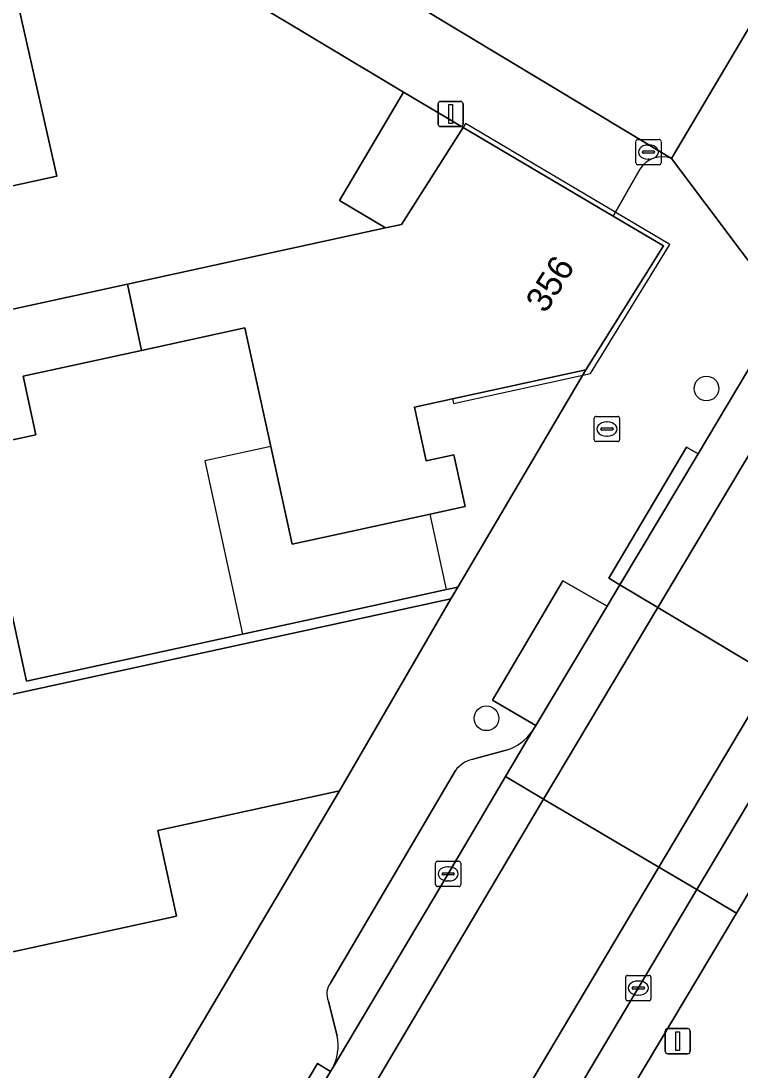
# Model space of a CAD drawing. Extents: x 160554 to 161248, y 385329 to 386506.
# Drawn here: x 160800.82 to 160829.3, y 385754.9 to 385796.49 of the extents above; entities that cross this region are included whole.
import ezdxf

# ---------------------------------------------------------------- set-up
doc = ezdxf.new("R2010")
doc.units = 0
for name, color, linetype in [('IMGEO_Boom', 7, 'Continuous'), ('IMGEO_Brandkraan', 7, 'Continuous'), ('IMGEO_Erf', 7, 'Continuous'), ('IMGEO_Kolk', 7, 'Continuous'), ('IMGEO_Lichtmast', 7, 'Continuous'), ('IMGEO_Pand', 7, 'Continuous'), ('IMGEO_Pand_nummerreeks', 7, 'Continuous'), ('IMGEO_Pand_overbouw', 7, 'Continuous'), ('IMGEO_Parkeervlak_open', 7, 'Continuous'), ('IMGEO_Rijbaan_lokaal_gesloten', 7, 'Continuous'), ('IMGEO_Rijbaan_lokaal_open', 7, 'Continuous'), ('IMGEO_Voetpad_open', 7, 'Continuous')]:
    doc.layers.add(name, color=color, linetype=linetype)

msp = doc.modelspace()

# ---------------------------------------------------------------- linework, layer by layer
at = {"layer": 'IMGEO_Boom'}
for centre in [(160827.97, 385781.916), (160819.254, 385768.842)]:
    msp.add_circle(centre, 0.489, dxfattribs=at)
at = {"layer": 'IMGEO_Brandkraan'}
for p, q in [((160823.526, 385779.884), (160823.526, 385780.736)), ((160823.601, 385780.81), (160824.453, 385780.81)), ((160824.014, 385780.59), (160824.039, 385780.59)), ((160824.527, 385780.736), (160824.527, 385779.884)), ((160823.785, 385780.304), (160823.785, 385780.316)), ((160824.223, 385780.267), (160823.825, 385780.267)), ((160823.828, 385780.353), (160824.226, 385780.353)), ((160824.037, 385780.03), (160824.012, 385780.03)), ((160824.269, 385780.316), (160824.269, 385780.304)), ((160824.453, 385779.81), (160823.601, 385779.81))]:
    msp.add_line(p, q, dxfattribs=at)
for points in [[(160823.526, 385779.884), (160823.526, 385780.736)], [(160823.601, 385780.81), (160824.453, 385780.81)], [(160824.527, 385780.736), (160824.527, 385779.884)], [(160824.453, 385779.81), (160823.601, 385779.81)]]:
    msp.add_lwpolyline(points, dxfattribs=at)
for centre, radius, start, end in [((160823.603, 385780.734), 0.0765, 91.552, 178.448), ((160823.603, 385780.734), 0.0765, 91.552, 178.448), ((160824.451, 385780.734), 0.0765, 1.552, 88.448), ((160824.451, 385780.734), 0.0765, 1.552, 88.448), ((160823.825, 385780.313), 0.0403, 85.8775, 175.7526), ((160823.822, 385780.303), 0.0366, 178.938, 274.7102), ((160824.226, 385780.31), 0.043, 264.8664, 352.4533), ((160824.23, 385780.315), 0.0386, 1.7309, 96.639), ((160823.603, 385779.886), 0.0765, 181.552, 268.448), ((160823.603, 385779.886), 0.0765, 181.552, 268.448), ((160824.451, 385779.886), 0.0765, 271.552, 358.448), ((160824.451, 385779.886), 0.0765, 271.552, 358.448)]:
    msp.add_arc(centre, radius, start, end, dxfattribs=at)
for centre, major_axis, ratio, start_param, end_param in [((160824.013, 385780.31), (-0.387, 0.002), 0.722429, 4.712389, 7.853982), ((160824.038, 385780.31), (-0.39, 0.002), 0.717154, 1.570796, 4.712389)]:
    msp.add_ellipse(centre, major_axis=major_axis, ratio=ratio, start_param=start_param, end_param=end_param, dxfattribs=at)
at = {"layer": 'IMGEO_Erf'}
for points in [[(160797.582, 385839.533), (160777.43, 385835.122), (160782.162, 385813.51), (160796.35, 385816.614), (160798.295, 385807.928), (160800.447, 385798.314), (160802.235, 385790.33), (160796.019, 385788.976), (160795.316, 385792.204), (160792.549, 385791.601), (160793.252, 385788.373), (160788.797, 385787.403), (160789.812, 385782.742), (160805.036, 385786.057), (160815.262, 385788.283), (160813.432, 385789.365), (160815.971, 385793.66), (160806.321, 385799.472)], [(160810.713, 385779.615), (160809.689, 385784.319), (160805.594, 385783.427), (160800.899, 385782.404), (160801.404, 385780.084), (160799.016, 385779.564), (160801.029, 385770.319), (160809.595, 385772.184), (160813.231, 385772.976), (160817.678, 385773.945), (160818.116, 385774.04), (160823.188, 385782.657), (160817.906, 385781.507), (160816.398, 385781.179), (160816.438, 385780.994), (160816.862, 385779.044), (160817.967, 385779.285), (160818.413, 385777.239), (160817.026, 385776.937), (160813.931, 385776.263), (160811.555, 385775.746)], [(160813.435, 385765.968), (160806.234, 385764.4), (160806.975, 385761), (160794.84, 385758.356), (160796.659, 385750), (160798.402, 385741.996), (160799.383, 385742.21), (160803.991, 385750)]]:
    msp.add_lwpolyline(points, close=True, dxfattribs=at)
at = {"layer": 'IMGEO_Kolk'}
for p, q in [((160825.172, 385790.864), (160825.172, 385791.716)), ((160825.247, 385791.79), (160826.099, 385791.79)), ((160826.173, 385791.716), (160826.173, 385790.864)), ((160825.431, 385791.284), (160825.431, 385791.296)), ((160825.869, 385791.247), (160825.471, 385791.247)), ((160825.474, 385791.333), (160825.872, 385791.333)), ((160825.66, 385791.57), (160825.685, 385791.57)), ((160825.915, 385791.296), (160825.915, 385791.284)), ((160825.683, 385791.01), (160825.658, 385791.01)), ((160826.099, 385790.79), (160825.247, 385790.79)), ((160817.238, 385762.248), (160817.238, 385763.1)), ((160817.313, 385763.174), (160818.165, 385763.174)), ((160818.239, 385763.1), (160818.239, 385762.248)), ((160817.497, 385762.668), (160817.497, 385762.68)), ((160817.935, 385762.631), (160817.537, 385762.631)), ((160817.54, 385762.717), (160817.938, 385762.717)), ((160817.726, 385762.954), (160817.751, 385762.954)), ((160817.981, 385762.68), (160817.981, 385762.668)), ((160818.165, 385762.174), (160817.313, 385762.174)), ((160817.749, 385762.394), (160817.724, 385762.394)), ((160824.771, 385757.722), (160824.771, 385758.574)), ((160824.846, 385758.648), (160825.698, 385758.648)), ((160825.259, 385758.428), (160825.284, 385758.428)), ((160825.772, 385758.574), (160825.772, 385757.722)), ((160825.03, 385758.142), (160825.03, 385758.154)), ((160825.468, 385758.105), (160825.07, 385758.105)), ((160825.073, 385758.191), (160825.471, 385758.191)), ((160825.514, 385758.154), (160825.514, 385758.142)), ((160825.698, 385757.648), (160824.846, 385757.648)), ((160825.282, 385757.868), (160825.257, 385757.868))]:
    msp.add_line(p, q, dxfattribs=at)
for points in [[(160825.172, 385790.864), (160825.172, 385791.716)], [(160825.247, 385791.79), (160826.099, 385791.79)], [(160826.173, 385791.716), (160826.173, 385790.864)], [(160826.099, 385790.79), (160825.247, 385790.79)], [(160817.238, 385762.248), (160817.238, 385763.1)], [(160817.313, 385763.174), (160818.165, 385763.174)], [(160818.239, 385763.1), (160818.239, 385762.248)], [(160818.165, 385762.174), (160817.313, 385762.174)], [(160824.771, 385757.722), (160824.771, 385758.574)], [(160824.846, 385758.648), (160825.698, 385758.648)], [(160825.772, 385758.574), (160825.772, 385757.722)], [(160825.698, 385757.648), (160824.846, 385757.648)]]:
    msp.add_lwpolyline(points, dxfattribs=at)
for centre, radius, start, end in [((160825.249, 385791.714), 0.0765, 91.552, 178.448), ((160825.249, 385791.714), 0.0765, 91.552, 178.448), ((160826.097, 385791.714), 0.0765, 1.552, 88.448), ((160826.097, 385791.714), 0.0765, 1.552, 88.448), ((160825.471, 385791.293), 0.0403, 85.8775, 175.7526), ((160825.468, 385791.283), 0.0366, 178.938, 274.7102), ((160825.872, 385791.29), 0.043, 264.8664, 352.4533), ((160825.876, 385791.295), 0.0386, 1.7309, 96.639), ((160825.249, 385790.866), 0.0765, 181.552, 268.448), ((160825.249, 385790.866), 0.0765, 181.552, 268.448), ((160826.097, 385790.866), 0.0765, 271.552, 358.448), ((160826.097, 385790.866), 0.0765, 271.552, 358.448), ((160817.315, 385763.098), 0.0765, 91.552, 178.448), ((160817.315, 385763.098), 0.0765, 91.552, 178.448), ((160818.163, 385763.098), 0.0765, 1.552, 88.448), ((160818.163, 385763.098), 0.0765, 1.552, 88.448), ((160817.537, 385762.677), 0.0403, 85.8775, 175.7526), ((160817.534, 385762.667), 0.0366, 178.938, 274.7102), ((160817.938, 385762.674), 0.043, 264.8664, 352.4533), ((160817.942, 385762.679), 0.0386, 1.7309, 96.639), ((160817.315, 385762.25), 0.0765, 181.552, 268.448), ((160817.315, 385762.25), 0.0765, 181.552, 268.448), ((160818.163, 385762.25), 0.0765, 271.552, 358.448), ((160818.163, 385762.25), 0.0765, 271.552, 358.448), ((160824.848, 385758.572), 0.0765, 91.552, 178.448), ((160824.848, 385758.572), 0.0765, 91.552, 178.448), ((160825.696, 385758.572), 0.0765, 1.552, 88.448), ((160825.696, 385758.572), 0.0765, 1.552, 88.448), ((160825.07, 385758.151), 0.0403, 85.8775, 175.7526), ((160825.067, 385758.141), 0.0366, 178.938, 274.7102), ((160825.471, 385758.148), 0.043, 264.8664, 352.4533), ((160825.475, 385758.153), 0.0386, 1.7309, 96.639), ((160824.848, 385757.724), 0.0765, 181.552, 268.448), ((160824.848, 385757.724), 0.0765, 181.552, 268.448), ((160825.696, 385757.724), 0.0765, 271.552, 358.448), ((160825.696, 385757.724), 0.0765, 271.552, 358.448)]:
    msp.add_arc(centre, radius, start, end, dxfattribs=at)
for centre, major_axis, ratio, start_param, end_param in [((160825.659, 385791.29), (-0.387, 0.002), 0.722429, 4.712389, 7.853982), ((160825.684, 385791.29), (-0.39, 0.002), 0.717154, 1.570796, 4.712389), ((160817.725, 385762.674), (-0.387, 0.002), 0.722429, 4.712389, 7.853982), ((160817.75, 385762.674), (-0.39, 0.002), 0.717154, 1.570796, 4.712389), ((160825.258, 385758.148), (-0.387, 0.002), 0.722429, 4.712389, 7.853982), ((160825.283, 385758.148), (-0.39, 0.002), 0.717154, 1.570796, 4.712389)]:
    msp.add_ellipse(centre, major_axis=major_axis, ratio=ratio, start_param=start_param, end_param=end_param, dxfattribs=at)
at = {"layer": 'IMGEO_Lichtmast'}
for p, q in [((160817.338, 385792.401), (160817.338, 385793.201)), ((160817.338, 385793.201), (160817.338, 385792.401)), ((160817.438, 385793.301), (160818.228, 385793.301)), ((160818.228, 385793.301), (160817.438, 385793.301)), ((160818.328, 385793.201), (160818.328, 385792.401)), ((160818.328, 385792.401), (160818.328, 385793.201)), ((160818.228, 385792.301), (160817.438, 385792.301)), ((160817.438, 385792.301), (160818.228, 385792.301)), ((160826.335, 385755.644), (160826.335, 385756.444)), ((160826.335, 385756.444), (160826.335, 385755.644)), ((160826.435, 385756.544), (160827.225, 385756.544)), ((160827.225, 385756.544), (160826.435, 385756.544)), ((160827.325, 385756.444), (160827.325, 385755.644)), ((160827.325, 385755.644), (160827.325, 385756.444)), ((160827.225, 385755.544), (160826.435, 385755.544)), ((160826.435, 385755.544), (160827.225, 385755.544))]:
    msp.add_line(p, q, dxfattribs=at)
for points in [[(160817.758, 385793.176), (160817.908, 385793.176), (160817.908, 385792.426), (160817.758, 385792.426), (160817.758, 385793.176)], [(160826.755, 385756.419), (160826.905, 385756.419), (160826.905, 385755.669), (160826.755, 385755.669), (160826.755, 385756.419)]]:
    msp.add_lwpolyline(points, dxfattribs=at)
for centre, start, end in [((160817.438, 385793.201), 90, 180), ((160817.438, 385793.201), 90, 180), ((160818.228, 385793.201), 0, 90), ((160818.228, 385793.201), 360, 90), ((160817.438, 385792.401), 180, 270), ((160817.438, 385792.401), 180, 270), ((160818.228, 385792.401), 270, 0), ((160818.228, 385792.401), 270, 0), ((160826.435, 385756.444), 90, 180), ((160826.435, 385756.444), 90, 180), ((160827.225, 385756.444), 0, 90), ((160827.225, 385756.444), 360, 90), ((160826.435, 385755.644), 180, 270), ((160826.435, 385755.644), 180, 270), ((160827.225, 385755.644), 270, 0), ((160827.225, 385755.644), 270, 0)]:
    msp.add_arc(centre, 0.1, start, end, dxfattribs=at)
at = {"layer": 'IMGEO_Pand'}
for points in [[(160802.235, 385790.33), (160800.447, 385798.314), (160772.013, 385792.125), (160774.791, 385779.47), (160789.812, 385782.742), (160788.797, 385787.403), (160793.252, 385788.373), (160792.549, 385791.601), (160795.316, 385792.204), (160796.019, 385788.976)], [(160818.326, 385792.268), (160815.971, 385793.66), (160813.432, 385789.365), (160815.262, 385788.283), (160815.895, 385788.421)], [(160826.273, 385787.57), (160824.271, 385788.754), (160818.326, 385792.268), (160815.895, 385788.421), (160815.262, 385788.283), (160805.036, 385786.057), (160805.594, 385783.427), (160809.689, 385784.319), (160810.713, 385779.615), (160811.555, 385775.746), (160813.931, 385776.263), (160817.026, 385776.937), (160818.413, 385777.239), (160817.967, 385779.285), (160816.862, 385779.044), (160816.438, 385780.994), (160816.398, 385781.179), (160817.906, 385781.507), (160823.188, 385782.657)], [(160799.016, 385779.564), (160801.404, 385780.084), (160800.899, 385782.404), (160805.594, 385783.427), (160805.036, 385786.057), (160789.812, 385782.742), (160774.791, 385779.47), (160777.992, 385764.891), (160817.846, 385773.574), (160818.116, 385774.04), (160817.678, 385773.945), (160813.231, 385772.976), (160809.595, 385772.184), (160801.029, 385770.319)], [(160780.116, 385755.219), (160794.84, 385758.356), (160806.975, 385761), (160806.234, 385764.4), (160813.435, 385765.968), (160817.846, 385773.574), (160777.992, 385764.891)]]:
    msp.add_lwpolyline(points, close=True, dxfattribs=at)
at = {"layer": 'IMGEO_Pand_overbouw'}
for points in [[(160818.422, 385792.42), (160818.326, 385792.268), (160824.271, 385788.754), (160826.273, 385787.57), (160823.188, 385782.657), (160817.906, 385781.507), (160817.946, 385781.323), (160823.375, 385782.511), (160826.522, 385787.632)], [(160810.713, 385779.615), (160808.101, 385779.046), (160809.595, 385772.184), (160813.231, 385772.976), (160817.678, 385773.945), (160817.026, 385776.937), (160813.931, 385776.263), (160811.555, 385775.746)]]:
    msp.add_lwpolyline(points, close=True, dxfattribs=at)
at = {"layer": 'IMGEO_Parkeervlak_open'}
for points in [[(160796.064, 385861.476), (160795.385, 385864.625), (160792.241, 385863.947), (160792.688, 385861.904), (160794.287, 385854.597), (160795.61, 385848.538), (160795.644, 385848.382), (160797.582, 385839.533), (160806.321, 385799.472), (160815.971, 385793.66), (160818.326, 385792.268), (160824.271, 385788.754), (160825.347, 385790.624)], [(160826.58, 385791.032), (160811.768, 385799.966)], [(160813.147, 385754.952), (160817.739, 385762.674), (160820.012, 385766.535), (160821.075, 385768.341)], [(160820.035, 385767.583), (160818.681, 385767.213)], [(160818.023, 385766.77), (160813.088, 385758.371)], [(160820.622, 385746.796), (160822.533, 385750), (160829.162, 385761.115), (160827.585, 385762.049), (160825.271, 385758.149), (160820.43, 385750), (160815.067, 385740.874), (160814.4, 385739.76), (160813.682, 385738.667), (160812.914, 385737.599), (160812.097, 385736.559), (160811.233, 385735.551), (160810.325, 385734.578), (160809.373, 385733.642), (160806.634, 385731.089)], [(160812.998, 385757.621), (160813.341, 385756.256)]]:
    msp.add_lwpolyline(points, dxfattribs=at)
for points in [[(160821.205, 385768.562), (160824.031, 385773.282), (160822.278, 385774.286), (160819.492, 385769.555)], [(160832.093, 385769.616), (160827.585, 385762.049), (160829.162, 385761.115), (160833.651, 385768.686)]]:
    msp.add_lwpolyline(points, close=True, dxfattribs=at)
for centre, radius, start, end in [((160826.207, 385790.092), 1.011, 68.3545, 148.2643), ((160819.503, 385769.405), 1.898, 286.2669, 325.9057), ((160819, 385766.028), 1.227, 105.0905, 142.8105), ((160813.653, 385757.923), 0.721, 141.5802, 204.7343), ((160811.469, 385755.868), 1.912, 331.368, 11.708)]:
    msp.add_arc(centre, radius, start, end, dxfattribs=at)
at = {"layer": 'IMGEO_Rijbaan_lokaal_gesloten'}
for points in [[(160824.538, 385774.128), (160826.04, 385773.231), (160868.007, 385843.619), (160866.508, 385844.523), (160866.264, 385844.178), (160857.435, 385829.369), (160848.222, 385813.893), (160841.702, 385802.983), (160838.179, 385797.023), (160837.349, 385795.634), (160831.171, 385785.249), (160827.643, 385779.323)], [(160830.591, 385770.513), (160872.512, 385840.903), (160868.007, 385843.619), (160826.04, 385773.231)], [(160820.012, 385766.535), (160821.517, 385765.643), (160826.04, 385773.231), (160824.538, 385774.128), (160824.031, 385773.282), (160821.205, 385768.562), (160821.075, 385768.341)], [(160827.585, 385762.049), (160832.093, 385769.616), (160830.591, 385770.513), (160826.079, 385762.941)], [(160786.538, 385725.881), (160786.566, 385725.887), (160796.373, 385728.143), (160800.425, 385729.673), (160803.02, 385731.041), (160806.707, 385733.629), (160808.89, 385735.618), (160810.876, 385737.835), (160812.627, 385740.241), (160814.174, 385742.894), (160826.079, 385762.941), (160821.517, 385765.643), (160810.143, 385746.407), (160807.834, 385742.548), (160805.812, 385739.758), (160802.996, 385737.152), (160800.052, 385735.188), (160797.144, 385733.839), (160793.868, 385732.951), (160792.717, 385732.681), (160785.425, 385731.134), (160785.368, 385731.122)]]:
    msp.add_lwpolyline(points, close=True, dxfattribs=at)
for points in [[(160795.515, 385735.207), (160792.548, 385734.443), (160792.335, 385734.389), (160784.996, 385732.789), (160785.368, 385731.122), (160785.425, 385731.134), (160792.717, 385732.681), (160793.868, 385732.951), (160797.144, 385733.839), (160800.052, 385735.188), (160802.996, 385737.152), (160805.812, 385739.758), (160807.834, 385742.548), (160810.143, 385746.407), (160821.517, 385765.643), (160820.012, 385766.535), (160817.739, 385762.674), (160813.147, 385754.952), (160813.077, 385754.834), (160810.19, 385750), (160809.229, 385748.39), (160808.639, 385747.301), (160806.45, 385743.688)], [(160806.634, 385731.089), (160809.373, 385733.642), (160810.325, 385734.578), (160811.233, 385735.551), (160812.097, 385736.559), (160812.914, 385737.599), (160813.682, 385738.667), (160814.4, 385739.76), (160815.067, 385740.874), (160820.43, 385750), (160825.271, 385758.149), (160827.585, 385762.049), (160826.079, 385762.941), (160814.174, 385742.894), (160812.627, 385740.241), (160810.876, 385737.835), (160808.89, 385735.618), (160806.707, 385733.629), (160803.02, 385731.041)]]:
    msp.add_lwpolyline(points, dxfattribs=at)
at = {"layer": 'IMGEO_Rijbaan_lokaal_open'}
msp.add_lwpolyline([(160811.768, 385799.966), (160826.58, 385791.032), (160830.011, 385796.806), (160829.07, 385797.436), (160825.508, 385799.535), (160821.27, 385801.917), (160820.814, 385802.173), (160816.317, 385804.701)], dxfattribs=at)
msp.add_lwpolyline([(160826.04, 385773.231), (160821.517, 385765.643), (160826.079, 385762.941), (160830.591, 385770.513)], close=True, dxfattribs=at)
at = {"layer": 'IMGEO_Voetpad_open'}
for points in [[(160836.92, 385795.889), (160833.466, 385795.918), (160830.011, 385796.806), (160826.58, 385791.032), (160830.742, 385785.504)], [(160827.643, 385779.323), (160827.177, 385779.594), (160824.107, 385774.4), (160824.538, 385774.128)], [(160809.229, 385748.39), (160810.19, 385750), (160813.077, 385754.834), (160812.559, 385755.156), (160809.5, 385750), (160808.72, 385748.685)]]:
    msp.add_lwpolyline(points, close=True, dxfattribs=at)
for points in [[(160821.205, 385768.562), (160819.492, 385769.555), (160822.278, 385774.286), (160824.031, 385773.282), (160824.538, 385774.128), (160824.107, 385774.4), (160827.177, 385779.594), (160827.643, 385779.323), (160831.171, 385785.249), (160830.742, 385785.504), (160826.58, 385791.032)], [(160825.347, 385790.624), (160824.271, 385788.754), (160826.273, 385787.57), (160823.188, 385782.657), (160818.116, 385774.04), (160817.846, 385773.574), (160813.435, 385765.968), (160803.991, 385750), (160799.383, 385742.21), (160797.328, 385738.735), (160786.072, 385736.282)], [(160836.348, 385773.221), (160833.651, 385768.686), (160829.162, 385761.115), (160822.533, 385750), (160820.622, 385746.796)], [(160821.075, 385768.341), (160821.205, 385768.562)], [(160818.681, 385767.213), (160820.035, 385767.583)], [(160813.088, 385758.371), (160818.023, 385766.77)], [(160813.341, 385756.256), (160812.998, 385757.621)], [(160806.45, 385743.688), (160808.639, 385747.301), (160809.229, 385748.39), (160808.72, 385748.685), (160809.5, 385750), (160812.559, 385755.156), (160813.077, 385754.834), (160813.147, 385754.952)]]:
    msp.add_lwpolyline(points, dxfattribs=at)
for centre, radius, start, end in [((160826.207, 385790.092), 1.011, 68.3545, 148.2643), ((160819.503, 385769.405), 1.898, 286.2669, 325.9057), ((160819, 385766.028), 1.227, 105.0905, 142.8105), ((160813.653, 385757.923), 0.721, 141.5802, 204.7343), ((160811.469, 385755.868), 1.912, 331.368, 11.708)]:
    msp.add_arc(centre, radius, start, end, dxfattribs=at)

# ---------------------------------------------------------------- texts
at = {"layer": 'IMGEO_Pand_nummerreeks'}
msp.add_text('356', height=1, rotation=57.8745, dxfattribs=at).set_placement((160821.595, 385784.86))

doc.saveas('drawing.dxf')
